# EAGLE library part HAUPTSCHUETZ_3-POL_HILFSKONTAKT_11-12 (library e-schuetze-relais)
Hauptschütz 3-pol. mit Hilfskontakt Öffner
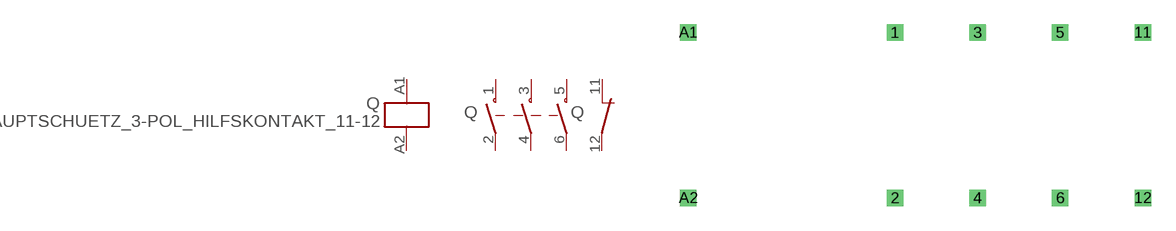
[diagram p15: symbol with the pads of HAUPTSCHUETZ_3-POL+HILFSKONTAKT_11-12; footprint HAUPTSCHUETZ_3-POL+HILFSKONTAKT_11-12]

Designator prefix Q; gates 1=SPULE 3=OEFFNER G$1=SCHLIESSER_HAUPTSCHUETZ_3-POL

## HAUPTSCHUETZ_3-POL_HILFSKONTAKT_11-12  [HAUPTSCHUETZ_3-POL+HILFSKONTAKT_11-12]
1  G$1:1  pas
2  G$1:2  pas
3  G$1:3  pas
4  G$1:4  pas
5  G$1:5  pas
6  G$1:6  pas
11  3:1  pas
12  3:2  pas
A1  1:A1  in
A2  1:A2  in

## Footprint HAUPTSCHUETZ_3-POL+HILFSKONTAKT_11-12 (pad centres in mm)
Dummy
drill 0.5 pad 1 square: 1 2.54,2.54; 2 2.54,-7.62; 3 7.62,2.54; 4 7.62,-7.62; 5 12.7,2.54; 6 12.7,-7.62; 11 17.78,2.54; 12 17.78,-7.62; A1 -10.16,2.54; A2 -10.16,-7.62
